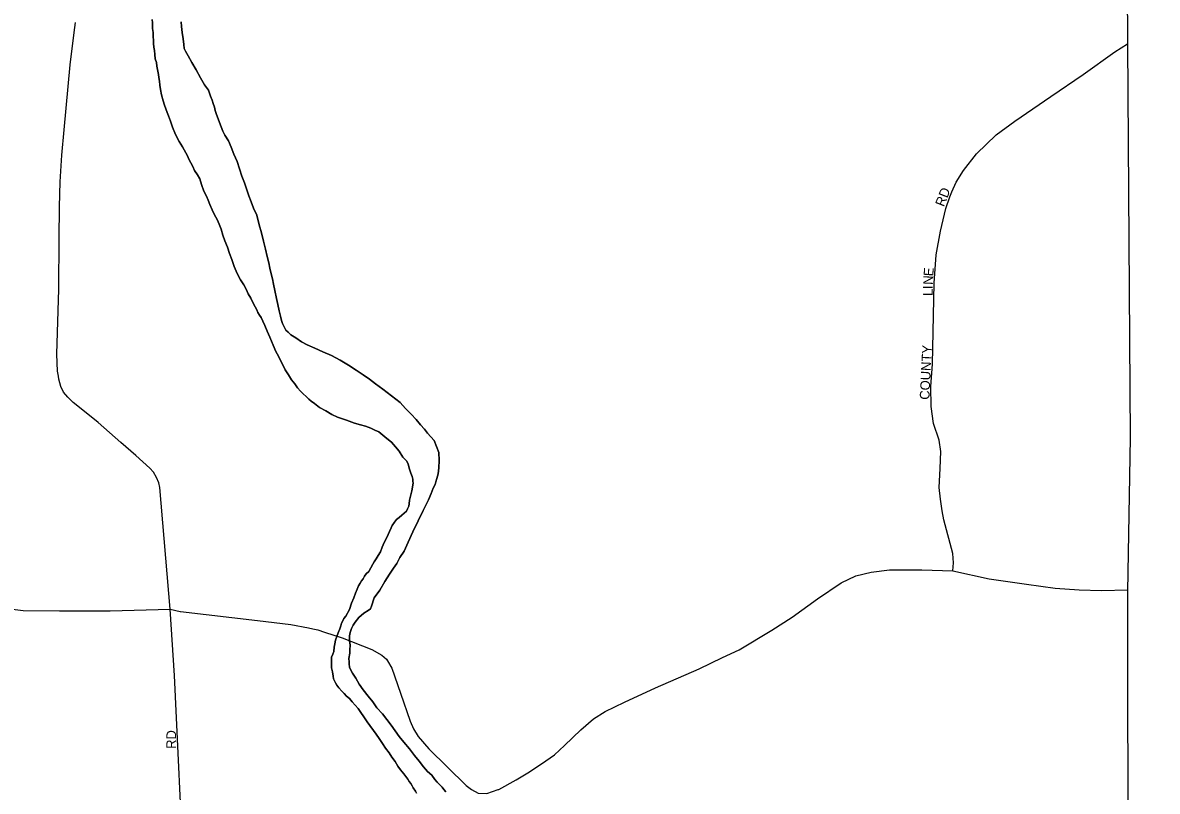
# Model space of a CAD drawing. Extents: x -561 to 1170, y 0 to 846.
# Drawn here: x 450.89 to 466.69, y 249.01 to 259.72 of the extents above; entities that cross this region are included whole.
import ezdxf

# ---------------------------------------------------------------- set-up
doc = ezdxf.new("R2010")
doc.units = 0
for name, color, linetype in [('GM_X_City_Street', 7, 'Continuous'), ('GM_X_City_Street_Text', 7, 'Continuous'), ('GM_X_County', 7, 'Continuous'), ('GM_X_Major_River', 7, 'Continuous'), ('GM_X_State_Route', 7, 'Continuous')]:
    doc.layers.add(name, color=color, linetype=linetype)

msp = doc.modelspace()

# ---------------------------------------------------------------- linework, layer by layer
at = {"layer": 'GM_X_City_Street'}
for points in [[(451.388, 254.795), (451.377, 254.869), (451.366, 255.103), (451.394, 256.007), (451.4, 256.714), (451.405, 257.158), (451.411, 257.503), (451.434, 257.876), (451.467, 258.229), (451.551, 259.133), (451.61, 259.585), (451.625, 259.725)], [(463.844, 252.086), (463.852, 252.196), (463.846, 252.327), (463.719, 252.797), (463.696, 252.922), (463.675, 253.082), (463.654, 253.248), (463.67, 253.512), (463.676, 253.746), (463.656, 253.904), (463.573, 254.14), (463.542, 254.377), (463.54, 254.655), (463.563, 254.966), (463.584, 256.092), (463.614, 256.487), (463.674, 256.815), (463.747, 257.133), (463.805, 257.297), (463.83, 257.366), (463.893, 257.5), (463.991, 257.663), (464.175, 257.896), (464.448, 258.16), (464.706, 258.347), (465.209, 258.693), (465.659, 258.998), (466.102, 259.316), (466.276, 259.428)], [(452.944, 251.55), (452.802, 253.245), (452.787, 253.311), (452.755, 253.384), (452.714, 253.458), (452.661, 253.517), (452.468, 253.69), (452.256, 253.873), (451.942, 254.154), (451.705, 254.343), (451.592, 254.43), (451.518, 254.505), (451.461, 254.575), (451.422, 254.651), (451.394, 254.755), (451.388, 254.795)], [(453.079, 241.027), (453.253, 244.099), (453.257, 245.113), (453.139, 247.779), (453.003, 250.63), (452.944, 251.55)]]:
    msp.add_lwpolyline(points, dxfattribs=at)
at = {"layer": 'GM_X_County'}
msp.add_lwpolyline([(466.148, 281.711), (466.276, 259.428), (466.313, 253.936), (466.279, 251.796), (466.28, 247.567), (466.28, 245.072), (466.408, 237.742), (466.848, 237.719), (471.546, 237.752), (478.016, 237.883), (478.739, 226.426), (478.848, 224.815), (479.164, 220.147), (479.331, 217.621), (477.752, 217.584), (469.804, 217.395), (466.368, 217.313), (466.37, 216.798), (466.375, 215.749), (466.382, 214.541), (466.407, 209.575)], dxfattribs=at)
at = {"layer": 'GM_X_Major_River'}
for points in [[(452.694, 259.766), (452.7, 259.718), (452.701, 259.642), (452.707, 259.582), (452.707, 259.522), (452.713, 259.479), (452.713, 259.43), (452.719, 259.381), (452.725, 259.333), (452.731, 259.278), (452.737, 259.219), (452.754, 259.165), (452.76, 259.116), (452.771, 259.045), (452.782, 258.997), (452.788, 258.959), (452.794, 258.904), (452.8, 258.85), (452.811, 258.791), (452.823, 258.715), (452.845, 258.634), (452.867, 258.574), (452.884, 258.52), (452.901, 258.471), (452.923, 258.422), (452.951, 258.347), (452.979, 258.266)], [(452.979, 258.266), (452.951, 258.347), (452.923, 258.422), (452.901, 258.471), (452.884, 258.52), (452.867, 258.574), (452.845, 258.634), (452.823, 258.715), (452.811, 258.791), (452.8, 258.85), (452.794, 258.904), (452.788, 258.959), (452.782, 258.997), (452.771, 259.045), (452.76, 259.116), (452.754, 259.165), (452.737, 259.219), (452.731, 259.278), (452.725, 259.333), (452.719, 259.381), (452.713, 259.43), (452.713, 259.479), (452.707, 259.522), (452.707, 259.582), (452.701, 259.642), (452.7, 259.718), (452.694, 259.766)], [(455.72, 254.757), (455.633, 254.816), (455.535, 254.881), (455.426, 254.95), (455.311, 255.02), (455.192, 255.084), (455.072, 255.138), (454.958, 255.186), (454.854, 255.234), (454.772, 255.277), (454.696, 255.331), (454.625, 255.374), (454.587, 255.411), (454.554, 255.438), (454.527, 255.492), (454.51, 255.53), (454.493, 255.574), (454.482, 255.633), (454.465, 255.709), (454.443, 255.796), (454.426, 255.877), (454.403, 255.991), (454.386, 256.077), (454.369, 256.153), (454.352, 256.224), (454.335, 256.3), (454.318, 256.375), (454.296, 256.462), (454.273, 256.565), (454.245, 256.679), (454.217, 256.793), (454.183, 256.906), (454.15, 257.042), (454.105, 257.139), (454.072, 257.226), (454.039, 257.307), (454.011, 257.393), (453.978, 257.491), (453.944, 257.583), (453.911, 257.686), (453.877, 257.789), (453.833, 257.891), (453.794, 257.989), (453.755, 258.075), (453.706, 258.156), (453.678, 258.21), (453.656, 258.27), (453.59, 258.443), (453.573, 258.497), (453.562, 258.546), (453.545, 258.595), (453.528, 258.643), (453.506, 258.698), (453.478, 258.779), (453.423, 258.854), (453.368, 258.952), (453.308, 259.065), (453.247, 259.168), (453.197, 259.26), (453.159, 259.325), (453.142, 259.363), (453.136, 259.417), (453.125, 259.498), (453.113, 259.585), (453.102, 259.666), (453.096, 259.731)], [(453.096, 259.731), (453.102, 259.666), (453.113, 259.585), (453.125, 259.498), (453.136, 259.417), (453.142, 259.363), (453.159, 259.325), (453.197, 259.26), (453.247, 259.168), (453.308, 259.065), (453.368, 258.952), (453.423, 258.854), (453.478, 258.779), (453.506, 258.698), (453.528, 258.643), (453.545, 258.595), (453.562, 258.546), (453.573, 258.497), (453.59, 258.443), (453.656, 258.27), (453.678, 258.21), (453.706, 258.156), (453.755, 258.075), (453.794, 257.989), (453.833, 257.891), (453.877, 257.789), (453.911, 257.686), (453.944, 257.583), (453.978, 257.491), (454.011, 257.393), (454.039, 257.307), (454.072, 257.226), (454.105, 257.139), (454.15, 257.042), (454.183, 256.906), (454.217, 256.793), (454.245, 256.679), (454.273, 256.565), (454.296, 256.462), (454.318, 256.375), (454.335, 256.3), (454.352, 256.224), (454.369, 256.153), (454.386, 256.077), (454.403, 255.991), (454.426, 255.877), (454.443, 255.796), (454.465, 255.709), (454.482, 255.633), (454.493, 255.574), (454.51, 255.53), (454.527, 255.492), (454.554, 255.438), (454.587, 255.411), (454.625, 255.374), (454.696, 255.331), (454.772, 255.277), (454.854, 255.234), (454.958, 255.186), (455.072, 255.138), (455.192, 255.084), (455.311, 255.02), (455.426, 254.95), (455.535, 254.881), (455.633, 254.816), (455.72, 254.757)], [(452.979, 258.266), (453.017, 258.163), (453.072, 258.065), (453.117, 257.99), (453.188, 257.865), (453.205, 257.822), (453.232, 257.768), (453.26, 257.719), (453.282, 257.66), (453.326, 257.6), (453.359, 257.546), (453.381, 257.465), (453.415, 257.373), (453.453, 257.303), (453.476, 257.249), (453.498, 257.189), (453.531, 257.114), (453.564, 257.043), (453.597, 256.978), (453.625, 256.913), (453.653, 256.843), (453.68, 256.762), (453.708, 256.681), (453.742, 256.594), (453.769, 256.507), (453.803, 256.421), (453.836, 256.323), (453.88, 256.226), (453.925, 256.139), (453.969, 256.069), (454.002, 256.01), (454.029, 255.945), (454.068, 255.885), (454.101, 255.815), (454.128, 255.761), (454.15, 255.723), (454.167, 255.685), (454.189, 255.648), (454.211, 255.615), (454.233, 255.561), (454.261, 255.502), (454.294, 255.426), (454.333, 255.339), (454.377, 255.231), (454.416, 255.139), (454.454, 255.074), (454.482, 255.015), (454.515, 254.955), (454.548, 254.885), (454.592, 254.815), (454.636, 254.744), (454.68, 254.69), (454.719, 254.636), (454.762, 254.588), (454.877, 254.475), (454.91, 254.448), (454.954, 254.416), (455.025, 254.362), (455.112, 254.314), (455.194, 254.265), (455.275, 254.228), (455.346, 254.201), (455.4, 254.185), (455.438, 254.169), (455.514, 254.143), (455.596, 254.121), (455.667, 254.1), (455.737, 254.074), (455.797, 254.047), (455.852, 254.02), (455.906, 253.977), (455.961, 253.928), (456.026, 253.88), (456.081, 253.815), (456.136, 253.751), (456.185, 253.67), (456.235, 253.616), (456.257, 253.578), (456.274, 253.518), (456.296, 253.448), (456.313, 253.399), (456.324, 253.361), (456.324, 253.334), (456.33, 253.307), (456.309, 253.198), (456.278, 253.068), (456.273, 253.019), (456.267, 252.986), (456.252, 252.948), (456.236, 252.916), (456.171, 252.861), (456.133, 252.828), (456.096, 252.801), (456.069, 252.763), (456.037, 252.719), (456.021, 252.686), (455.957, 252.54), (455.925, 252.48), (455.898, 252.414), (455.872, 252.349), (455.84, 252.3)], [(455.84, 252.3), (455.872, 252.349), (455.898, 252.414), (455.925, 252.48), (455.957, 252.54), (456.021, 252.686), (456.037, 252.719), (456.069, 252.763), (456.096, 252.801), (456.133, 252.828), (456.171, 252.861), (456.236, 252.916), (456.252, 252.948), (456.267, 252.986), (456.273, 253.019), (456.278, 253.068), (456.309, 253.198), (456.33, 253.307), (456.324, 253.334), (456.324, 253.361), (456.313, 253.399), (456.296, 253.448), (456.274, 253.518), (456.257, 253.578), (456.235, 253.616), (456.185, 253.67), (456.136, 253.751), (456.081, 253.815), (456.026, 253.88), (455.961, 253.928), (455.906, 253.977), (455.852, 254.02), (455.797, 254.047), (455.737, 254.074), (455.667, 254.1), (455.596, 254.121), (455.514, 254.143), (455.438, 254.169), (455.4, 254.185), (455.346, 254.201), (455.275, 254.228), (455.194, 254.265), (455.112, 254.314), (455.025, 254.362), (454.954, 254.416), (454.91, 254.448), (454.877, 254.475), (454.762, 254.588), (454.719, 254.636), (454.68, 254.69), (454.636, 254.744), (454.592, 254.815), (454.548, 254.885), (454.515, 254.955), (454.482, 255.015), (454.454, 255.074), (454.416, 255.139), (454.377, 255.231), (454.333, 255.339), (454.294, 255.426), (454.261, 255.502), (454.233, 255.561), (454.211, 255.615), (454.189, 255.648), (454.167, 255.685), (454.15, 255.723), (454.128, 255.761), (454.101, 255.815), (454.068, 255.885), (454.029, 255.945), (454.002, 256.01), (453.969, 256.069), (453.925, 256.139), (453.88, 256.226), (453.836, 256.323), (453.803, 256.421), (453.769, 256.507), (453.742, 256.594), (453.708, 256.681), (453.68, 256.762), (453.653, 256.843), (453.625, 256.913), (453.597, 256.978), (453.564, 257.043), (453.531, 257.114), (453.498, 257.189), (453.476, 257.249), (453.453, 257.303), (453.415, 257.373), (453.381, 257.465), (453.359, 257.546), (453.326, 257.6), (453.282, 257.66), (453.26, 257.719), (453.232, 257.768), (453.205, 257.822), (453.188, 257.865), (453.117, 257.99), (453.072, 258.065), (453.017, 258.163), (452.979, 258.266)], [(456.785, 249.008), (456.758, 249.04), (456.731, 249.072), (456.698, 249.105), (456.665, 249.142), (456.632, 249.18), (456.588, 249.24), (456.528, 249.293), (456.473, 249.358), (456.413, 249.434), (456.347, 249.515), (456.276, 249.606), (456.199, 249.698), (456.133, 249.779), (456.079, 249.855), (456.024, 249.936), (455.963, 250.017), (455.903, 250.092), (455.821, 250.179), (455.766, 250.26), (455.7, 250.341), (455.634, 250.427), (455.579, 250.508), (455.53, 250.589), (455.486, 250.659), (455.458, 250.713), (455.442, 250.746), (455.436, 250.789), (455.436, 250.816), (455.435, 250.865), (455.445, 250.941), (455.445, 250.984), (455.45, 251.05), (455.444, 251.109), (455.443, 251.174), (455.448, 251.207), (455.454, 251.24), (455.469, 251.283), (455.491, 251.327), (455.523, 251.37), (455.571, 251.436), (455.641, 251.496), (455.7, 251.534), (455.733, 251.556), (455.749, 251.594), (455.786, 251.708), (455.866, 251.817), (455.935, 251.937), (455.999, 252.041), (456.053, 252.122), (456.101, 252.188), (456.144, 252.27), (456.203, 252.362), (456.261, 252.487), (456.325, 252.629), (456.399, 252.781), (456.469, 252.928), (456.543, 253.075), (456.58, 253.162), (456.607, 253.238), (456.633, 253.287), (456.644, 253.325), (456.66, 253.374), (456.675, 253.439), (456.686, 253.521), (456.69, 253.624), (456.684, 253.733), (456.656, 253.819), (456.623, 253.9), (456.573, 253.954), (456.529, 254.003), (456.486, 254.057), (456.431, 254.121), (456.371, 254.192), (456.299, 254.267), (456.223, 254.348), (456.146, 254.429), (455.906, 254.617), (455.802, 254.692), (455.72, 254.757)], [(455.72, 254.757), (455.802, 254.692), (455.906, 254.617), (456.146, 254.429), (456.223, 254.348), (456.299, 254.267), (456.371, 254.192), (456.431, 254.121), (456.486, 254.057), (456.529, 254.003), (456.573, 253.954), (456.623, 253.9), (456.656, 253.819), (456.684, 253.733), (456.69, 253.624), (456.686, 253.521), (456.675, 253.439), (456.66, 253.374), (456.644, 253.325), (456.633, 253.287), (456.607, 253.238), (456.58, 253.162), (456.543, 253.075), (456.469, 252.928), (456.399, 252.781), (456.325, 252.629), (456.261, 252.487), (456.203, 252.362), (456.144, 252.27), (456.101, 252.188), (456.053, 252.122), (455.999, 252.041), (455.935, 251.937), (455.866, 251.817), (455.786, 251.708), (455.749, 251.594), (455.733, 251.556), (455.7, 251.534), (455.641, 251.496), (455.571, 251.436), (455.523, 251.37), (455.491, 251.327), (455.469, 251.283), (455.454, 251.24), (455.448, 251.207), (455.443, 251.174), (455.444, 251.109), (455.45, 251.05), (455.445, 250.984), (455.445, 250.941), (455.435, 250.865), (455.436, 250.816), (455.436, 250.789), (455.442, 250.746), (455.458, 250.713), (455.486, 250.659), (455.53, 250.589), (455.579, 250.508), (455.634, 250.427), (455.7, 250.341), (455.766, 250.26), (455.821, 250.179), (455.903, 250.092), (455.963, 250.017), (456.024, 249.936), (456.079, 249.855), (456.133, 249.779), (456.199, 249.698), (456.276, 249.606), (456.347, 249.515), (456.413, 249.434), (456.473, 249.358), (456.528, 249.293), (456.588, 249.24), (456.632, 249.18), (456.665, 249.142), (456.698, 249.105), (456.731, 249.072), (456.758, 249.04), (456.785, 249.008)], [(455.84, 252.3), (455.813, 252.251), (455.786, 252.213), (455.765, 252.18), (455.738, 252.126), (455.712, 252.077), (455.674, 252.044), (455.653, 252.011), (455.631, 251.973), (455.61, 251.946), (455.589, 251.913), (455.567, 251.875), (455.551, 251.832), (455.525, 251.777), (455.504, 251.712), (455.472, 251.636), (455.44, 251.549), (455.392, 251.456), (455.365, 251.423), (455.349, 251.391), (455.333, 251.358), (455.323, 251.32), (455.307, 251.277), (455.286, 251.222), (455.264, 251.173), (455.249, 251.119), (455.238, 251.07), (455.228, 251.021), (455.223, 250.961), (455.212, 250.923), (455.191, 250.885), (455.191, 250.847), (455.192, 250.793), (455.192, 250.733), (455.204, 250.679), (455.215, 250.62), (455.221, 250.582), (455.249, 250.527), (455.265, 250.495), (455.292, 250.457), (455.336, 250.409), (455.369, 250.376), (455.402, 250.339), (455.44, 250.306), (455.479, 250.263), (455.522, 250.215), (455.561, 250.166), (455.599, 250.112), (455.643, 250.053), (455.687, 249.982), (455.813, 249.81), (455.857, 249.75), (455.901, 249.68), (455.945, 249.615), (455.994, 249.55), (456.033, 249.491), (456.077, 249.432), (456.115, 249.367), (456.154, 249.313), (456.198, 249.259), (456.225, 249.221), (456.253, 249.183), (456.275, 249.151), (456.296, 249.124), (456.313, 249.091), (456.33, 249.064), (456.362, 249.016), (456.374, 248.989)], [(456.374, 248.989), (456.362, 249.016), (456.33, 249.064), (456.313, 249.091), (456.296, 249.124), (456.275, 249.151), (456.253, 249.183), (456.225, 249.221), (456.198, 249.259), (456.154, 249.313), (456.115, 249.367), (456.077, 249.432), (456.033, 249.491), (455.994, 249.55), (455.945, 249.615), (455.901, 249.68), (455.857, 249.75), (455.813, 249.81), (455.687, 249.982), (455.643, 250.053), (455.599, 250.112), (455.561, 250.166), (455.522, 250.215), (455.479, 250.263), (455.44, 250.306), (455.402, 250.339), (455.369, 250.376), (455.336, 250.409), (455.292, 250.457), (455.265, 250.495), (455.249, 250.527), (455.221, 250.582), (455.215, 250.62), (455.204, 250.679), (455.192, 250.733), (455.192, 250.793), (455.191, 250.847), (455.191, 250.885), (455.212, 250.923), (455.223, 250.961), (455.228, 251.021), (455.238, 251.07), (455.249, 251.119), (455.264, 251.173), (455.286, 251.222), (455.307, 251.277), (455.323, 251.32), (455.333, 251.358), (455.349, 251.391), (455.365, 251.423), (455.392, 251.456), (455.44, 251.549), (455.472, 251.636), (455.504, 251.712), (455.525, 251.777), (455.551, 251.832), (455.567, 251.875), (455.589, 251.913), (455.61, 251.946), (455.631, 251.973), (455.653, 252.011), (455.674, 252.044), (455.712, 252.077), (455.738, 252.126), (455.765, 252.18), (455.786, 252.213), (455.813, 252.251), (455.84, 252.3)]]:
    msp.add_lwpolyline(points, dxfattribs=at)
at = {"layer": 'GM_X_State_Route'}
for points in [[(448.309, 252.835), (448.696, 252.68), (449.542, 252.336), (449.738, 252.227), (450.034, 252.009), (450.362, 251.734), (450.546, 251.619), (450.639, 251.574), (450.75, 251.55), (450.899, 251.533), (451.403, 251.528), (452.111, 251.527), (452.944, 251.55), (453.084, 251.52)], [(457.513, 249.039), (457.521, 249.041), (457.765, 249.174), (457.926, 249.273), (458.117, 249.396), (458.295, 249.524), (458.438, 249.655), (458.662, 249.87), (458.841, 250.024), (459.001, 250.125), (459.273, 250.255), (459.705, 250.456), (460.313, 250.723), (460.635, 250.878), (460.871, 250.984), (461.324, 251.261), (461.605, 251.442), (461.962, 251.698), (462.289, 251.919), (462.495, 252.014), (462.706, 252.065), (462.962, 252.1), (463.415, 252.1), (463.844, 252.086), (464.351, 251.976), (464.872, 251.899), (465.271, 251.843), (465.603, 251.819), (465.917, 251.814), (466.28, 251.822)], [(453.084, 251.52), (453.088, 251.519), (454.161, 251.394), (454.624, 251.336), (454.872, 251.294), (454.931, 251.28)], [(454.931, 251.28), (455, 251.262), (455.094, 251.232), (455.341, 251.153), (455.752, 250.992), (455.893, 250.909), (455.958, 250.854), (455.972, 250.83)], [(455.972, 250.83), (456.032, 250.732), (456.151, 250.382), (456.289, 249.99), (456.335, 249.883), (456.398, 249.78), (456.546, 249.607), (457.069, 249.094), (457.142, 249.039), (457.235, 248.991), (457.353, 248.984), (457.513, 249.039)]]:
    msp.add_lwpolyline(points, dxfattribs=at)

# ---------------------------------------------------------------- texts
at = {"layer": 'GM_X_City_Street_Text'}
for s, rotation, p in [('RD', 68.7471, (463.72, 257.148)), ('E', 85.8443, (463.571, 256.185)), ('N', 87.0263, (463.565, 256.067)), ('L', 89.8907, (463.564, 255.915)), ('I', 89.4319, (463.565, 256.009)), ('COUNTY', 87.1801, (463.517, 254.466)), ('RD', 90, (453.027, 249.606))]:
    msp.add_text(s, height=0.135, rotation=rotation, dxfattribs=at).set_placement(p)

doc.saveas('drawing.dxf')
